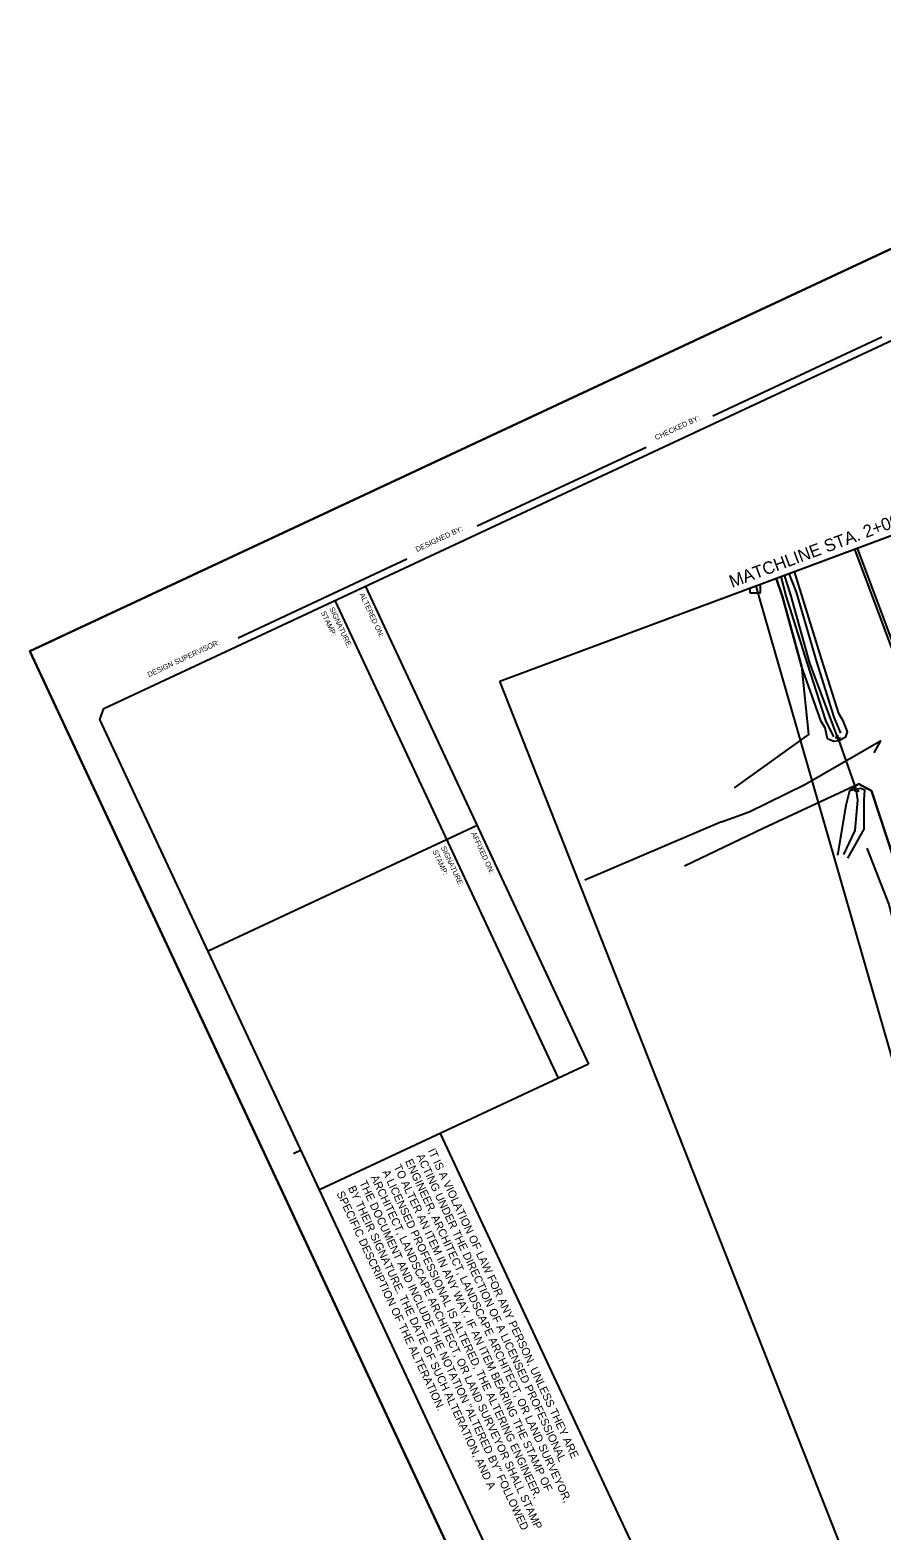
# Model space of a CAD drawing. Extents: x 1040364 to 1041050, y 1127298 to 1128100.
# Drawn here: x 1040363.9 to 1040619.4, y 1127649.8 to 1128099.9 of the extents above; entities that cross this region are included whole.
import ezdxf

# ---------------------------------------------------------------- set-up
doc = ezdxf.new("R2010")
doc.units = 0
for name, color, linetype in [('clip boundary', 7, 'Continuous'), ('DCP', 7, 'Continuous'), ('DD', 7, 'Continuous'), ('DINV', 7, 'Continuous'), ('LABL', 7, 'Continuous'), ('LAWA', 7, 'Continuous'), ('LELB', 7, 'Continuous'), ('MHB', 7, 'Continuous'), ('MPM', 7, 'Continuous'), ('NML_P', 7, 'Continuous'), ('NML_P_T', 7, 'Continuous'), ('PE', 7, 'Continuous'), ('RTR', 7, 'Continuous'), ('SHEET_BORDER', 7, 'Continuous'), ('SHEET_BORDER_CUT', 7, 'Continuous'), ('SHEET_BORDER_STAMPBOX', 7, 'Continuous'), ('SHEET_BORDER_TEXT', 7, 'Continuous'), ('STSEW', 7, 'Continuous')]:
    doc.layers.add(name, color=color, linetype=linetype)

msp = doc.modelspace()

# ---------------------------------------------------------------- linework, layer by layer
at = {"layer": 'clip boundary'}
for points in [[(1040762.51, 1128099.9), (1041050.31, 1127483.8), (1040651.66, 1127297.58), (1040363.86, 1127913.67)], [(1040504.79, 1127904.67), (1040760.34, 1127999.71), (1040984.84, 1127512.73), (1040710.81, 1127382.18)]]:
    msp.add_lwpolyline(points, close=True, dxfattribs=at)
at = {"layer": 'DCP'}
msp.add_line((1040606.15, 1127887.65), (1040611.79, 1127871.79), dxfattribs=at)
at = {"layer": 'DD'}
for points in [[(1040606.15, 1127887.65), (1040597.71, 1127910.07), (1040591.93, 1127930.84), (1040590.16, 1127936.41)], [(1040607.93, 1127852.66), (1040611.35, 1127859.86), (1040612.1, 1127869.01), (1040611.79, 1127871.79)]]:
    msp.add_lwpolyline(points, dxfattribs=at)
at = {"layer": 'DINV'}
for p, q in [((1040606.15, 1127887.65), (1040606.15, 1127888.44)), ((1040606.15, 1127887.65), (1040605.36, 1127887.65)), ((1040606.15, 1127887.65), (1040606.94, 1127887.65)), ((1040606.15, 1127887.65), (1040606.15, 1127886.86)), ((1040611.79, 1127871.79), (1040611.01, 1127871.79)), ((1040611.79, 1127871.79), (1040611.79, 1127872.58)), ((1040611.79, 1127871.79), (1040612.58, 1127871.79)), ((1040611.79, 1127871.79), (1040611.79, 1127871))]:
    msp.add_line(p, q, dxfattribs=at)
at = {"layer": 'LABL'}
msp.add_lwpolyline([(1040587.68, 1127935.49), (1040589.51, 1127929.97)], dxfattribs=at)
at = {"layer": 'LAWA'}
for points in [[(1040589.51, 1127929.97), (1040595.25, 1127909.12), (1040597.39, 1127888.7), (1040575.02, 1127872.69)], [(1040583.91, 1127860.63), (1040612.35, 1127873.83), (1040616.26, 1127871.74), (1040629.69, 1127830.98), (1040637.02, 1127804.07), (1040651.71, 1127772.02), (1040660.81, 1127750.01), (1040670.93, 1127728.26), (1040683.43, 1127703.39), (1040695, 1127676.62), (1040706.92, 1127651.68), (1040723.86, 1127612.81), (1040738.89, 1127579.03), (1040755.95, 1127542.69), (1040767.31, 1127518.61), (1040755.88, 1127521.48)], [(1040560.2, 1127849.31), (1040583.91, 1127860.63)]]:
    msp.add_lwpolyline(points, dxfattribs=at)
at = {"layer": 'LELB'}
for points in [[(1040606.25, 1127886.81), (1040608.51, 1127887.97), (1040609.05, 1127889.46), (1040607.83, 1127892.55), (1040606.46, 1127894.97), (1040601.34, 1127911.09), (1040593.2, 1127937.55)], [(1040606.25, 1127886.81), (1040604.98, 1127886.59), (1040603.07, 1127887.39), (1040602.31, 1127890.62), (1040601.11, 1127892.56), (1040595.25, 1127909.12), (1040589.51, 1127929.97), (1040587.68, 1127935.49)], [(1040604.97, 1127887.99), (1040602.57, 1127892.85), (1040597.02, 1127909.96), (1040590.65, 1127930.26), (1040589.16, 1127936.04)], [(1040607.1, 1127889.09), (1040605.05, 1127893.82), (1040599.87, 1127910.46), (1040593.76, 1127931.38), (1040591.53, 1127936.92)], [(1040810.73, 1127429.78), (1040803.7, 1127447.62), (1040790.28, 1127475.04), (1040767.31, 1127518.61), (1040755.95, 1127542.69), (1040738.89, 1127579.03), (1040723.86, 1127612.81), (1040706.92, 1127651.68), (1040695, 1127676.62), (1040683.43, 1127703.39), (1040670.93, 1127728.26), (1040660.81, 1127750.01), (1040651.71, 1127772.02), (1040637.02, 1127804.07), (1040629.69, 1127830.98), (1040616.26, 1127871.74), (1040612.35, 1127873.83), (1040609.66, 1127871.77), (1040608.53, 1127867.34), (1040606.04, 1127852.48)], [(1040609.19, 1127851.55), (1040614.02, 1127860.28), (1040614, 1127868.95), (1040614.22, 1127871.94), (1040612.93, 1127872.48)], [(1040612.93, 1127872.48), (1040609.66, 1127871.77)], [(1040614.83, 1127854.62), (1040621.41, 1127837.65), (1040627.08, 1127815.86), (1040634.65, 1127795.46), (1040645.6, 1127772.71), (1040652.36, 1127757.32), (1040657.51, 1127737.76), (1040666.51, 1127712.78), (1040677.3, 1127685.09), (1040689.11, 1127653.1), (1040703.01, 1127617.33), (1040698.4, 1127596.43), (1040696.45, 1127571.66), (1040693.76, 1127556.81), (1040687.36, 1127532.93), (1040690.81, 1127510.27), (1040692.18, 1127477.93)]]:
    msp.add_lwpolyline(points, dxfattribs=at)
at = {"layer": 'MHB'}
msp.add_lwpolyline([(1040689.65, 1127435.84), (1040667.39, 1127529.05), (1040645.74, 1127710.89), (1040582.66, 1127929.61), (1040581.63, 1127933.24)], dxfattribs=at)
at = {"layer": 'MPM'}
for p, q in [((1040582.92, 1127931.17), (1040582.92, 1127933.72)), ((1040579.77, 1127932.55), (1040579.77, 1127931.17)), ((1040579.77, 1127931.17), (1040582.92, 1127931.17))]:
    msp.add_line(p, q, dxfattribs=at)
at = {"layer": 'NML_P'}
msp.add_line((1040504.79, 1127904.67), (1040760.34, 1127999.71), dxfattribs=at)
at = {"layer": 'PE'}
msp.add_lwpolyline([(1040827.22, 1127437.64), (1040826.9, 1127438.31), (1040805.61, 1127483.11), (1040784.16, 1127528.43), (1040762.74, 1127574.12), (1040748.8, 1127604.56), (1040741.94, 1127619.83), (1040735.2, 1127635.03), (1040721.93, 1127665.52), (1040708.68, 1127696.59), (1040702.17, 1127712.18), (1040695.93, 1127727.39), (1040683.59, 1127757.86), (1040671.21, 1127788.47), (1040665.07, 1127803.8), (1040658.98, 1127819.2), (1040646.94, 1127850.06), (1040634.62, 1127882.06), (1040628.54, 1127898.1), (1040611.22, 1127944.25)], dxfattribs=at)
at = {"layer": 'RTR'}
for points in [[(1040579.56, 1127865.52), (1040596.22, 1127873.64), (1040618.9, 1127886.8), (1040616.95, 1127883.16)], [(1040571.29, 1127862.48), (1040530.28, 1127844.95)], [(1040571.29, 1127862.48), (1040579.56, 1127865.52)]]:
    msp.add_lwpolyline(points, dxfattribs=at)
at = {"layer": 'SHEET_BORDER'}
for p, q in [((1040568.71, 1127984.23), (1040619.37, 1128007.9)), ((1040497.99, 1127951.19), (1040548.65, 1127974.86)), ((1040426.25, 1127917.69), (1040476.86, 1127941.32)), ((1040445.16, 1127764.02), (1040442.89, 1127762.96))]:
    msp.add_line(p, q, dxfattribs=at)
msp.add_lwpolyline([(1040652.69, 1127325.65), (1040649.37, 1127326.86), (1040384.85, 1127893.12), (1040386.05, 1127896.45), (1040761.49, 1128071.82), (1040764.81, 1128070.62), (1041029.33, 1127504.35), (1041028.12, 1127501.03)], close=True, dxfattribs=at)
at = {"layer": 'SHEET_BORDER_CUT'}
msp.add_lwpolyline([(1040363.86, 1127913.67), (1040651.66, 1127297.58), (1041050.31, 1127483.8), (1040762.51, 1128099.9)], close=True, dxfattribs=at)
msp.add_lwpolyline([(1040366.86, 1127907.27), (1040363.86, 1127913.67), (1040370.27, 1127916.67)], dxfattribs=at)
at = {"layer": 'SHEET_BORDER_STAMPBOX'}
for p, q in [((1040464.48, 1127933.08), (1040531.4, 1127789.82)), ((1040522.34, 1127785.59), (1040455.42, 1127928.85)), ((1040417.25, 1127823.76), (1040497.94, 1127861.45)), ((1040531.4, 1127789.82), (1040450.71, 1127752.12)), ((1040544.54, 1127645.78), (1040486.95, 1127769.05))]:
    msp.add_line(p, q, dxfattribs=at)
at = {"layer": 'STSEW'}
msp.add_lwpolyline([(1040828.27, 1127438.14), (1040827.96, 1127438.8), (1040806.65, 1127483.62), (1040785.12, 1127528.86), (1040763.78, 1127574.53), (1040749.77, 1127604.92), (1040742.86, 1127620.16), (1040736.1, 1127635.32), (1040722.83, 1127665.76), (1040716.16, 1127681.33), (1040702.99, 1127712.55), (1040690.38, 1127742.93), (1040684.16, 1127758.16), (1040671.9, 1127788.75), (1040665.82, 1127804.07), (1040659.73, 1127819.47), (1040647.66, 1127850.31), (1040635.42, 1127882.35), (1040629.38, 1127898.4), (1040612.07, 1127944.56)], dxfattribs=at)

# ---------------------------------------------------------------- texts
at = {"layer": 'NML_P_T'}
msp.add_text('MATCHLINE STA. 2+00 - SEE DWG. GNP-01', height=3.744, rotation=20.4011, dxfattribs=at).set_placement((1040574.42, 1127932.6))
at = {"layer": 'SHEET_BORDER_STAMPBOX'}
for s, height, p in [('ALTERED ON:', 1.5625, (1040462.65, 1127930.64)), ('STAMP:', 1.562, (1040451.07, 1127925.23)), ('SIGNATURE:', 1.562, (1040453.59, 1127926.4)), ('AFFIXED ON:', 1.5625, (1040496.11, 1127859)), ('STAMP:', 1.562, (1040484.54, 1127853.6)), ('SIGNATURE:', 1.562, (1040487.05, 1127854.77)), ('ACTING UNDER THE DIRECTION OF A LICENSED PROFESSIONAL ', 2.4, (1040479.71, 1127762.29)), ('IT IS A VIOLATION OF LAW FOR ANY PERSON, UNLESS THEY ARE ', 2.4, (1040483.14, 1127763.89)), ('A LICENSED PROFESSIONAL IS ALTERED, THE ALTERING ENGINEER, ', 2.4, (1040469.43, 1127757.49)), ('TO ALTER AN ITEM IN ANY WAY. IF AN ITEM BEARING THE STAMP OF ', 2.4, (1040472.86, 1127759.09)), ('ENGINEER, ARCHITECT, LANDSCAPE ARCHITECT, OR LAND SURVEYOR, ', 2.4, (1040476.29, 1127760.69)), ('BY THEIR SIGNATURE. THE DATE OF SUCH ALTERATION, AND A ', 2.4, (1040459.16, 1127752.69)), ('THE DOCUMENT AND INCLUDE THE NOTATION "ALTERED BY" FOLLOWED ', 2.4, (1040462.58, 1127754.29)), ('ARCHITECT, LANDSCAPE ARCHITECT, OR LAND SURVEYOR SHALL STAMP ', 2.4, (1040466.01, 1127755.89)), ('SPECIFIC DESCRIPTION OF THE ALTERATION.', 2.4, (1040455.73, 1127751.09))]:
    msp.add_text(s, height=height, rotation=295.0387, dxfattribs=at).set_placement(p)
at = {"layer": 'SHEET_BORDER_TEXT'}
for s, p in [('CHECKED BY:', (1040551.69, 1127976.86)), ('DESIGNED BY:', (1040479.96, 1127943.35)), ('DESIGN SUPERVISOR:', (1040399.53, 1127905.78))]:
    msp.add_text(s, height=1.5625, rotation=25.0387, dxfattribs=at).set_placement(p)

doc.saveas('drawing.dxf')
